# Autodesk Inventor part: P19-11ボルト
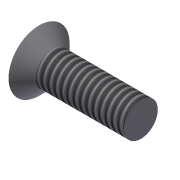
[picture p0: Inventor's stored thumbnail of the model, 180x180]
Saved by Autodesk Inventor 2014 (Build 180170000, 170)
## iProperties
Shininess: 64.0
Length Units: 11269
Angle Units: 11279
Time Units: 11290
Mass Units: 11284
Length Display Precision: 2
Angle Display Precision: 1
Created: 2002-10
Part Number: P19-11ボルト
Document SubType Name: ﾓﾃﾞﾘﾝｸﾞ
Designer: 株式会社富士システム
Stock Number: P19-11ボルト
Density: 1 g/cm^3
Material: 一般
Appearance: 既定
Density: 0.0
Volumn: 0.0
Area: 0.0
PropertySet Name: Model Information
Control State: 0
Master: False
Checked Out: False
Author: 株式会社富士システム
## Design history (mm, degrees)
sketch "ｽｹｯﾁ1"
  geometry: L1 (0, 0)-(0, -6); L2 (0, -6)-(2.677, -3.324); L3 (2.677, -3.324)-(20, -3.323); L4 (20, -3.323)-(20, 0); L5 (20, 0)-(0, 0); 1 further point
  constraints: 10 end point, 2 perpendicular, 1 coincident, 1 parallel, 1 vertical
  dimensions: "d14" = 45 deg angle of L5 L2; "d15" = 12 diameter of L1.end L5; "d16" = 20 distance between parallel lines of L4 L1; "d17" = 6.647 diameter of L3 L5
revolve "回転1" sketch "ｽｹｯﾁ1" stored, may be unused: angle "d5" = 90 deg
feature "ねじ1" dims "d6" = 10, "d7" = 0
sketch "ｽｹｯﾁ2"
  geometry: L1 (0, -6)-(0, 6); L2 (-6, 0)-(6, 0); L3 (-5.999, 0.718)-(-5.957, 0.718); L4 (-5.999, -0.718)-(-5.957, -0.718); L5 (5.957, -0.718)-(5.999, -0.718); L6 (5.957, 0.718)-(5.999, 0.718); L7 (0.718, -5.999)-(0.718, -5.957); L8 (-0.718, -5.999)-(-0.718, -5.957); L9 (-0.7, -3.938)-(-0.7, -0.7); L10 (0.7, -3.938)-(0.7, -0.7); L11 (0.7, 0.7)-(0.7, 3.938); L12 (0.718, 5.957)-(0.718, 5.999); L13 (-0.7, 0.7)-(-0.7, 3.938); L14 (-0.718, 5.957)-(-0.718, 5.999); L15 (-3.938, 0.7)-(-0.7, 0.7); L16 (0.7, 0.7)-(3.938, 0.7); L17 (-3.938, -0.7)-(-0.7, -0.7); L18 (0.7, -0.7)-(3.938, -0.7); A1 r 4 centre (0, 0) between (0.7, 3.938) and (-0.7, 3.938); A2 r 4 centre (0, 0) between (3.938, -0.7) and (3.938, 0.7); A3 r 4 centre (0, 0) between (-3.938, 0.7) and (-3.938, -0.7); A4 r 4 centre (0, 0) between (-0.7, -3.938) and (0.7, -3.938); 1 further point
  constraints: 36 end point, 8 point on circle, 4 centre point, 2 midpoint, 1 coincident, 1 perpendicular, 1 vertical, 13 other
extrude "押し出し1" cut sketch "ｽｹｯﾁ2" distance "d12" = 1; taper "d13" = 0 deg
node "ソリッド1"
node "ソリッド ボディ"
node "サーフェス ボディ"
other parameters: "d8" = 0.7, "d9" = 0.7 (= d8), "d10" = 0.7 (= d8), "d11" = 0.7 (= d8)
